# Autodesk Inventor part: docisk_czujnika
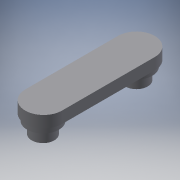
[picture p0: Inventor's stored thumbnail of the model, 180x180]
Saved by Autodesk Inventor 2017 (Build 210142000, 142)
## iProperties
Created: 2021-01
Part Number: docisk_czujnika
Material: Generic
Document SubType Name: Modeling
Designer: WindowsX
Density: 1 g/cm^3
Appearance: Default
Author: WindowsX
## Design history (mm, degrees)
sketch "Szkic1"
  geometry: L1 (0, 0)-(0, -16); L2 (-3.162, 0)-(-3.162, -16); L3 (3.162, -16)-(3.162, 0); A1 r 3.162 centre (0, 0) between (3.162, 0) and (-3.162, 0); A2 r 3.162 centre (0, -16) between (-3.162, -16) and (3.162, -16); 1 further point
  constraints: 8 end point, 4 point on circle, 4 tangent, 2 centre point, 1 midpoint, 1 parallel, 1 vertical
  dimensions: "d2" = 16 distance of L1.start L1.end
extrude "Wyciągnięcie proste1" new body sketch "Szkic1" distance "d0" = 2; taper "d1" = 0 deg
sketch "Szkic2"
  geometry: 3 further points
  constraints: 1 coincident
sketch "Szkic3"
  geometry: C1 r 2.75 at (0, -16.1); C2 r 2.75 at (0, 0); 1 further point
  constraints: 2 centre point, 1 coincident
  dimensions: "d3" = 5.5 diameter of C1; "d4" = 5.5 diameter of C2
extrude "Wyciągnięcie proste2" join sketch "Szkic3" distance "d5" = 1; taper "d6" = 0 deg
sketch "Szkic4"
  geometry: C1 r 1.95 at (0, 0); C2 r 2.75 at (0, -16.1) reference; C3 r 1.95 at (0, -16.1); 1 further point
  constraints: 2 centre point, 2 coincident
  dimensions: "d7" = 3.9 diameter of C1; "d8" = 3.9 diameter of C3
extrude "Wyciągnięcie proste3" join sketch "Szkic4" distance "d9" = 2; taper "d10" = 0 deg
node "Bryła1"
